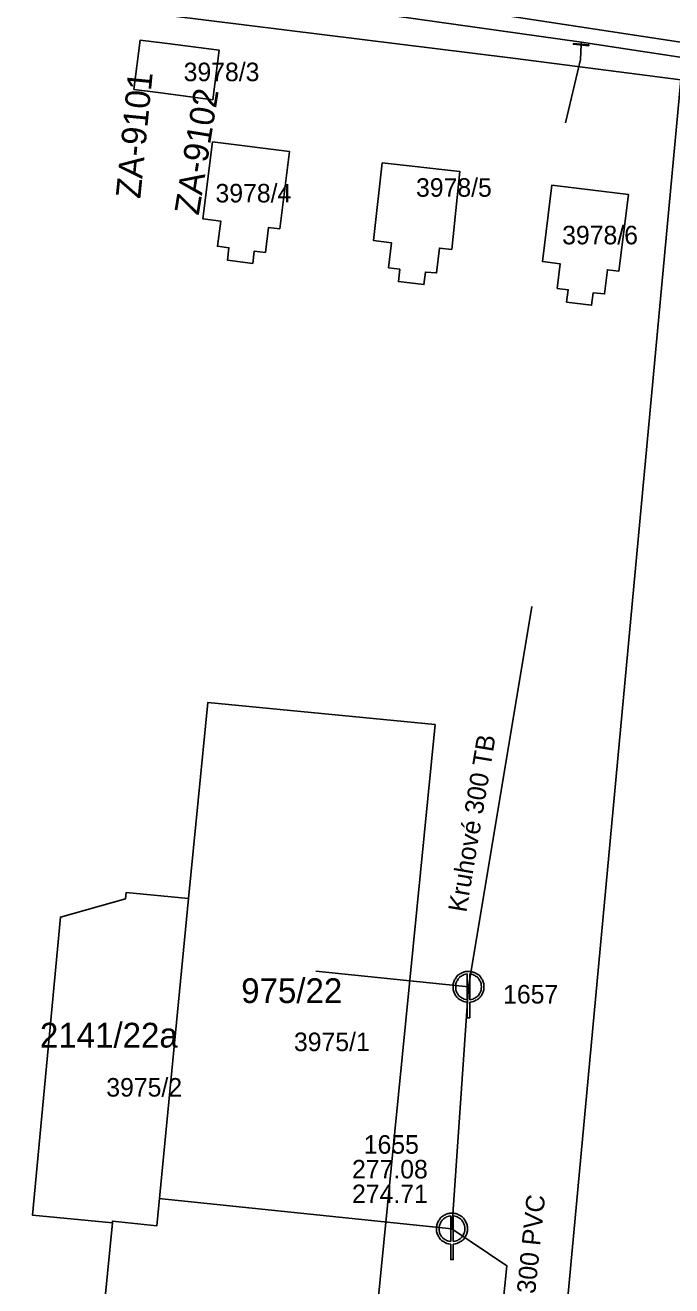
# Model space of a CAD drawing. Extents: x -570104 to -569328, y -1087857 to -1087418.
# Drawn here: x -569885.2 to -569832.9, y -1087663.8 to -1087561.8 of the extents above; entities that cross this region are included whole.
import ezdxf

# ---------------------------------------------------------------- set-up
doc = ezdxf.new("R2010")
doc.units = 0
for name, color, linetype in [('Adresní místo-text', 7, 'Continuous'), ('Armatura - popis', 7, 'Continuous'), ('Armatura vodovodní', 7, 'Continuous'), ('Default', 7, 'Continuous'), ('Kanalizační přípojka', 7, 'Continuous'), ('Kanalizační stoka', 7, 'Continuous'), ('Kanalizační šachta', 7, 'Continuous'), ('Parcela-polygon', 7, 'Continuous'), ('Parcela-text', 7, 'Continuous'), ('Popis kmenové stoky', 7, 'Continuous'), ('Popis šachty', 7, 'Continuous'), ('Vodovodní přípojka', 7, 'Continuous'), ('Vodovodní řad', 7, 'Continuous')]:
    doc.layers.add(name, color=color, linetype=linetype)

msp = doc.modelspace()

# ---------------------------------------------------------------- linework, layer by layer
at = {"layer": 'Armatura vodovodní'}
msp.add_lwpolyline([(-569839.62, -1087563.45), (-569840.87, -1087563.32), (-569840.86, -1087563.25), (-569839.61, -1087563.38), (-569839.62, -1087563.45)], dxfattribs=at)
at = {"layer": 'Default'}
for points in [[(-569849.46, -1087640.83), (-569849.72, -1087640.81), (-569849.98, -1087640.66), (-569850.28, -1087640.5), (-569850.45, -1087640.2), (-569850.61, -1087639.9), (-569850.61, -1087639.58), (-569850.61, -1087639.25), (-569850.44, -1087638.95), (-569850.27, -1087638.65), (-569849.98, -1087638.49), (-569849.68, -1087638.33), (-569849.36, -1087638.33), (-569849.05, -1087638.33), (-569848.75, -1087638.49), (-569848.45, -1087638.65), (-569848.28, -1087638.95), (-569848.11, -1087639.25), (-569848.11, -1087639.58), (-569848.11, -1087639.9), (-569848.27, -1087640.2), (-569848.44, -1087640.5), (-569848.74, -1087640.66), (-569849, -1087640.81), (-569849.26, -1087640.83)], [(-569849.46, -1087638.54), (-569849.66, -1087638.56), (-569849.88, -1087638.67), (-569850.12, -1087638.81), (-569850.26, -1087639.06), (-569850.4, -1087639.31), (-569850.4, -1087639.58), (-569850.4, -1087639.85), (-569850.27, -1087640.1), (-569850.13, -1087640.34), (-569849.88, -1087640.48), (-569849.67, -1087640.6), (-569849.46, -1087640.62)], [(-569849.26, -1087640.62), (-569849.05, -1087640.6), (-569848.84, -1087640.48), (-569848.59, -1087640.34), (-569848.45, -1087640.1), (-569848.32, -1087639.85), (-569848.32, -1087639.58), (-569848.32, -1087639.31), (-569848.46, -1087639.06), (-569848.6, -1087638.81), (-569848.85, -1087638.67), (-569849.06, -1087638.56), (-569849.26, -1087638.54)], [(-569850.8, -1087660.4), (-569851.06, -1087660.38), (-569851.32, -1087660.23), (-569851.62, -1087660.07), (-569851.79, -1087659.77), (-569851.95, -1087659.47), (-569851.95, -1087659.15), (-569851.95, -1087658.82), (-569851.78, -1087658.52), (-569851.61, -1087658.22), (-569851.32, -1087658.06), (-569851.02, -1087657.9), (-569850.7, -1087657.9), (-569850.39, -1087657.9), (-569850.09, -1087658.06), (-569849.79, -1087658.22), (-569849.62, -1087658.52), (-569849.45, -1087658.82), (-569849.45, -1087659.15), (-569849.45, -1087659.47), (-569849.61, -1087659.77), (-569849.78, -1087660.07), (-569850.08, -1087660.23), (-569850.34, -1087660.38), (-569850.6, -1087660.4)], [(-569850.8, -1087658.11), (-569851, -1087658.13), (-569851.22, -1087658.24), (-569851.46, -1087658.38), (-569851.6, -1087658.63), (-569851.74, -1087658.88), (-569851.74, -1087659.15), (-569851.74, -1087659.42), (-569851.61, -1087659.67), (-569851.47, -1087659.91), (-569851.22, -1087660.05), (-569851.01, -1087660.17), (-569850.8, -1087660.19)], [(-569850.6, -1087660.19), (-569850.39, -1087660.17), (-569850.18, -1087660.05), (-569849.93, -1087659.91), (-569849.79, -1087659.67), (-569849.66, -1087659.42), (-569849.66, -1087659.15), (-569849.66, -1087658.88), (-569849.8, -1087658.63), (-569849.94, -1087658.38), (-569850.19, -1087658.24), (-569850.4, -1087658.13), (-569850.6, -1087658.11)]]:
    msp.add_open_spline(points, degree=3, dxfattribs=at)
at = {"layer": 'Kanalizační přípojka'}
for points in [[(-569849.36, -1087639.58), (-569861.72, -1087638.32)], [(-569874.44, -1087656.71), (-569850.7, -1087659.15)]]:
    msp.add_lwpolyline(points, dxfattribs=at)
at = {"layer": 'Kanalizační stoka'}
for points in [[(-569844.23, -1087608.8), (-569849.36, -1087639.58)], [(-569849.36, -1087639.58), (-569850.7, -1087659.15)], [(-569850.7, -1087659.15), (-569846.25, -1087662.15), (-569847.64, -1087675.7)]]:
    msp.add_lwpolyline(points, dxfattribs=at)
at = {"layer": 'Kanalizační šachta'}
for points in [[(-569849.46, -1087640.62), (-569849.46, -1087638.54)], [(-569849.26, -1087638.54), (-569849.26, -1087640.62)], [(-569849.26, -1087640.83), (-569849.26, -1087642.08), (-569849.46, -1087642.08), (-569849.46, -1087640.83)], [(-569850.8, -1087660.19), (-569850.8, -1087658.11)], [(-569850.6, -1087658.11), (-569850.6, -1087660.19)], [(-569850.6, -1087660.4), (-569850.6, -1087661.65), (-569850.8, -1087661.65), (-569850.8, -1087660.4)]]:
    msp.add_lwpolyline(points, dxfattribs=at)
at = {"layer": 'Parcela-polygon'}
for points in [[(-570062.15, -1087532.37), (-570058.95, -1087532.84), (-570055.3, -1087533.38), (-570050.38, -1087532.72), (-570047.44, -1087532.16), (-570045.45, -1087531.92), (-570042.42, -1087531.77), (-570040.43, -1087531.83), (-569985.51, -1087540.02), (-569937.05, -1087547.13), (-569910.3, -1087551.09), (-569891.52, -1087553.88), (-569876.46, -1087556.17), (-569847.79, -1087560.78), (-569823.32, -1087564.49), (-569791.66, -1087569.4), (-569779.9, -1087571.5)], [(-569779.9, -1087571.5), (-569791.66, -1087569.4), (-569823.32, -1087564.49), (-569847.79, -1087560.78), (-569876.46, -1087556.17), (-569891.52, -1087553.88), (-569910.3, -1087551.09), (-569937.05, -1087547.13), (-569985.51, -1087540.02), (-570040.43, -1087531.83)], [(-569997.57, -1087542.16), (-569973.1, -1087545.91), (-569958.91, -1087548.36), (-569944.82, -1087550.4), (-569930.47, -1087552.71), (-569917.76, -1087554.5), (-569899.84, -1087557.01), (-569885.83, -1087559.47), (-569845.77, -1087564.46), (-569832.18, -1087566.19), (-569791.18, -1087573.2), (-569787.51, -1087573.83), (-569769.86, -1087576.85)], [(-569773.93, -1087685.9), (-569793.31, -1087679.13), (-569799.7, -1087677.5), (-569818.25, -1087673.66), (-569832.64, -1087670.5), (-569838.6, -1087668.62), (-569841.57, -1087667.29), (-569832.18, -1087566.19), (-569845.77, -1087564.46), (-569885.83, -1087559.47), (-569889.08, -1087593.3), (-569893.7, -1087641.34), (-569895.61, -1087660.17), (-569904.11, -1087737.43)], [(-569876.45, -1087566.98), (-569875.93, -1087562.98), (-569873.95, -1087563.24), (-569869.54, -1087563.81), (-569870.06, -1087567.81), (-569874.48, -1087567.23), (-569876.45, -1087566.98)], [(-569870.08, -1087571.22), (-569863.85, -1087572.01), (-569864.64, -1087578.25), (-569865.55, -1087578.14), (-569865.8, -1087580.16), (-569866.71, -1087580.05), (-569866.83, -1087581.05), (-569868.88, -1087580.79), (-569868.76, -1087579.79), (-569869.68, -1087579.67), (-569869.42, -1087577.63), (-569870.87, -1087577.44), (-569870.08, -1087571.22)], [(-569856.34, -1087572.92), (-569850.06, -1087573.63), (-569850.72, -1087579.92), (-569851.72, -1087579.81), (-569851.95, -1087581.82), (-569852.85, -1087581.76), (-569852.97, -1087582.77), (-569855.04, -1087582.53), (-569854.92, -1087581.52), (-569855.83, -1087581.41), (-569855.6, -1087579.38), (-569857.04, -1087579.2), (-569856.34, -1087572.92)], [(-569843.37, -1087580.91), (-569842.62, -1087574.73), (-569836.41, -1087575.49), (-569837.19, -1087581.67), (-569838.11, -1087581.56), (-569838.35, -1087583.52), (-569839.28, -1087583.44), (-569839.4, -1087584.44), (-569841.42, -1087584.18), (-569841.29, -1087583.19), (-569842.18, -1087583.08), (-569841.94, -1087581.09), (-569843.37, -1087580.91)], [(-569879, -1087666.88), (-569878.19, -1087658.66), (-569884.66, -1087658.04), (-569882.4, -1087633.93), (-569877.12, -1087632.46), (-569877.06, -1087631.94), (-569872.02, -1087632.44), (-569870.45, -1087616.57)], [(-569870.45, -1087616.57), (-569852.06, -1087618.36), (-569857.69, -1087675.23)]]:
    msp.add_lwpolyline(points, dxfattribs=at)
for points in [[(-569875.93, -1087562.98), (-569876.45, -1087566.98), (-569874.48, -1087567.23), (-569870.06, -1087567.81), (-569869.54, -1087563.81), (-569873.95, -1087563.24)], [(-569791.18, -1087573.2), (-569832.18, -1087566.19), (-569841.57, -1087667.29), (-569838.6, -1087668.62), (-569832.64, -1087670.5), (-569818.25, -1087673.66), (-569816.09, -1087655.34), (-569814.43, -1087640.08), (-569813.19, -1087633.59), (-569799.69, -1087633.53)], [(-569863.85, -1087572.01), (-569870.08, -1087571.22), (-569870.87, -1087577.44), (-569869.42, -1087577.63), (-569869.68, -1087579.67), (-569868.76, -1087579.79), (-569868.88, -1087580.79), (-569866.83, -1087581.05), (-569866.71, -1087580.05), (-569865.8, -1087580.16), (-569865.55, -1087578.14), (-569864.64, -1087578.25)], [(-569850.06, -1087573.63), (-569856.34, -1087572.92), (-569857.04, -1087579.2), (-569855.6, -1087579.38), (-569855.83, -1087581.41), (-569854.92, -1087581.52), (-569855.04, -1087582.53), (-569852.97, -1087582.77), (-569852.85, -1087581.76), (-569851.95, -1087581.82), (-569851.72, -1087579.81), (-569850.72, -1087579.92)], [(-569842.62, -1087574.73), (-569843.37, -1087580.91), (-569841.94, -1087581.09), (-569842.18, -1087583.08), (-569841.29, -1087583.19), (-569841.42, -1087584.18), (-569839.4, -1087584.44), (-569839.28, -1087583.44), (-569838.35, -1087583.52), (-569838.11, -1087581.56), (-569837.19, -1087581.67), (-569836.41, -1087575.49)], [(-569852.06, -1087618.36), (-569870.45, -1087616.57), (-569872.02, -1087632.44), (-569874.6, -1087658.92), (-569878.18, -1087658.53), (-569878.19, -1087658.66), (-569879, -1087666.88), (-569879.25, -1087666.84), (-569880.42, -1087679.81), (-569876.73, -1087680.27), (-569864.43, -1087681.34), (-569863.85, -1087674.7), (-569863.55, -1087674.72), (-569861.64, -1087674.89), (-569861.72, -1087675.89), (-569859.13, -1087676.17), (-569859.04, -1087675.12), (-569857.69, -1087675.23)], [(-569872.02, -1087632.44), (-569877.06, -1087631.94), (-569877.12, -1087632.46), (-569882.4, -1087633.93), (-569884.66, -1087658.04), (-569878.19, -1087658.66), (-569878.18, -1087658.53), (-569874.6, -1087658.92)]]:
    msp.add_lwpolyline(points, close=True, dxfattribs=at)
at = {"layer": 'Vodovodní přípojka'}
msp.add_lwpolyline([(-569840.22, -1087563.16), (-569840.24, -1087563.35), (-569840.29, -1087564.55), (-569841.52, -1087569.68)], dxfattribs=at)
at = {"layer": 'Vodovodní řad'}
msp.add_lwpolyline([(-569872.09, -1087558.64), (-569840.22, -1087563.16), (-569810.81, -1087567.64), (-569790.51, -1087570.61), (-569789.79, -1087570.73), (-569785.78, -1087571.59), (-569781.39, -1087572.37), (-569759.06, -1087576.8), (-569732.15, -1087585.98), (-569732.05, -1087586.05), (-569730.86, -1087586.83)], dxfattribs=at)

# ---------------------------------------------------------------- texts
at = {"layer": 'Adresní místo-text'}
for s, p in [('975/22', (-569867.76, -1087640.89)), ('2141/22a', (-569884.05, -1087644.49))]:
    msp.add_text(s, height=2, dxfattribs=at).set_placement(p)
at = {"layer": 'Armatura - popis'}
for s, rotation, p in [('ZA-9101', 84.327, (-569875.93, -1087575.86)), ('ZA-9102', 80.8666, (-569871.2, -1087577.21))]:
    msp.add_text(s, height=2, rotation=rotation, dxfattribs=at).set_placement(p)
at = {"layer": 'Parcela-text'}
for s, p in [('3978/3', (-569872.42, -1087566.31)), ('3978/5', (-569853.61, -1087575.66)), ('3978/4', (-569869.84, -1087576.12)), ('3978/6', (-569841.78, -1087579.51)), ('3975/1', (-569863.49, -1087644.78)), ('3975/2', (-569878.68, -1087648.46))]:
    msp.add_text(s, height=1.5, dxfattribs=at).set_placement(p)
at = {"layer": 'Popis kmenové stoky'}
for s, rotation, p in [('Kruhové 300 TB', 80.5419, (-569849.54, -1087633.61)), ('Kruhové 300 PVC', 84.1249, (-569844.79, -1087672.44))]:
    msp.add_text(s, height=1.5, rotation=rotation, dxfattribs=at).set_placement(p)
at = {"layer": 'Popis šachty'}
for s, p in [('1657', (-569846.56, -1087640.93)), ('1655', (-569857.84, -1087653.08)), ('277.08', (-569858.79, -1087655.08)), ('274.71', (-569858.79, -1087657.08))]:
    msp.add_text(s, height=1.5, dxfattribs=at).set_placement(p)

doc.saveas('drawing.dxf')
